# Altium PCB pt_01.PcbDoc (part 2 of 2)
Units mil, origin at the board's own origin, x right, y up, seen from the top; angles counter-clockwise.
Board outline 1456.69 x 1118.11 mil, 4 copper layers (Top Layer, med1, med2, Bottom Layer), stack 40.249 mil thick; 153 components, 173 nets, 567 pads, 147 vias.
Unrouted connection lines stored in the file: 22.
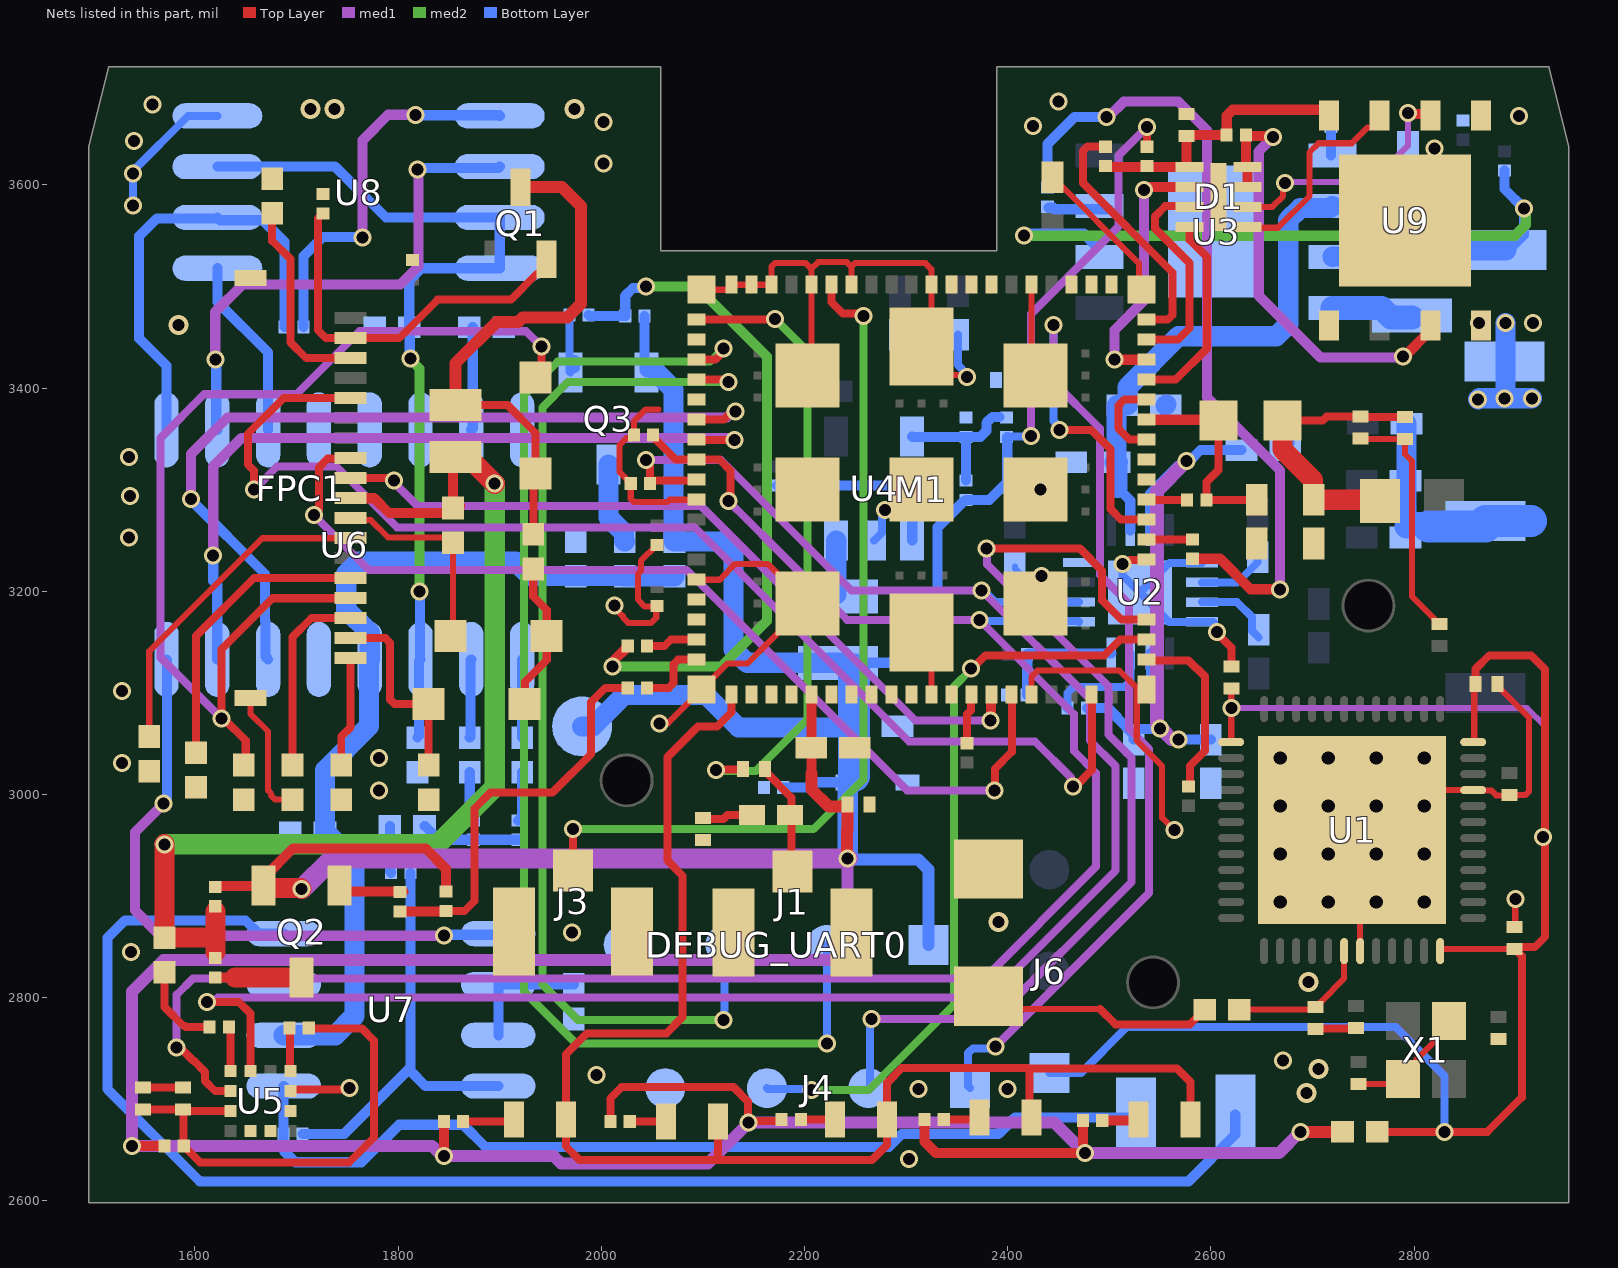
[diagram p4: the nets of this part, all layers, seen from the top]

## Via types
v1: diameter 17.72, hole 11.81, Top Layer to Bottom Layer, 121 vias
v2: diameter 25.98, hole 12.99, Top Layer to Bottom Layer, 16 vias
v3: diameter 19.68, hole 11.81, Top Layer to Bottom Layer, 8 vias
v4: diameter 25.59, hole 19.68, Top Layer to Bottom Layer, 1 vias
v5: diameter 27.56, hole 19.68, Top Layer to Bottom Layer, 1 vias

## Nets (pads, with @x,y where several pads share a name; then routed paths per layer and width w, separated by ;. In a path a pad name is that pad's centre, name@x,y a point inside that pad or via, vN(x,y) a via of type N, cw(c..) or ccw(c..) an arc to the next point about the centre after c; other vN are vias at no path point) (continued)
GND: C2.2 C3.2 C4.2 C5.2 C6.1 C7.2 C8.2 C9.2 C10.2 C11.2 C12.1 C13.2 C15.2 C16.2 C17.2 C19.2 C20.2 C21.1 C22.2 C23.2 C24.2 C26.2 C27.2 C28.2 C29.2 C30.2 C31.2 C32.2 C33.2 C34.2 C35.2 C43.2 C44.2 C45.1 C46.1 C48.1 C49.1 C50.1 C51.1 C52.1 C53.2 C54.2 C55.2 C56.1 C57.2 C58.2 C59.2 C63.1 D1.9 D3.1 D5.1 DEBUG_UART0.4 FPC1.8 FPC1.19 FPC1.20 GND.1 J1.2 J2.2 J3.2 J4.4 M1.1 M1.7 M1.13 M1.15 M1.20 M1.25 M1.30 M1.34 M1.36 M1.38 M1.39 M1.40 M1.41 M1.43 M1.46 M1.51 M1.55 M1.60 M1.66 M1.71 M1.76 M1.105 M1.106 M1.107 M1.108 M1.109 M1.110 M1.111 M1.112 M1.113 R9.1 R10.1 R14.1 R15.1 R17.2 R18.2 R19.2 R26.1 R28.2 R29.1 R30.2 U1.31 U1.45 U1.49 U2.1 U2.4 U2.17 U3.9 U4.2 U5.8 U5.9 U6.8 U6.13 U7.7 U8.4 U9.C4 U9.C5 U9.C8 U9.C9 X1.2 X1.4 | length 4047.3
  Top Layer w6: v1(1528,3102) v1@1530.24,3099.76 ; FPC1.20@1654.57,3094.78 1654.57,3079.43 1672,3062 1672,3004 1675,3001 1675,2999 1679,2995 1695.92,2995 C31.2@1696,2994.92 ; FPC1.8@1753,3271.94 1754.94,3270 1773,3270 1790,3253 1848.96,3253 C26.2@1854,3247.96 1854,3158.24 D3.1@1851.76,3156 ; v1(2013,3186) 2013,3183.83 2021.26,3175.57 2021.26,3174.24 2026.5,3169 2049,3169 2054,3174 2054,3184.49 R10.1@2054.51,3185 ; R17.2@2028.98,3304 2028.98,3291.02 2032,3288 2065,3288 2067.16,3290.16 M1.51@2093.54,3290.16 ; R17.2@2028.98,3306 2028.98,3306.41 2018,3317.39 2018,3344 2024.62,3350.62 2029.03,3350.62 2032,3353.59 R18.2@2032,3354 2032,3367.16 2043.84,3379 2056,3379 ; R10.1@2055,3185.49 R10.1@2054.51,3185 ; R9.1@2055,3245.49 2054.59,3245.49 2038.98,3229.88 2038.98,3219.98 2036,3217 2036,3192 2039,3189 2039,3188.51 2042.51,3185 R10.1@2054.51,3185 ; v1(2057,3070) 2065.31,3070 M1.60@2098.46,3103.15 2124.31,3129 2144,3129 M1.111@2202.8,3187.8 2163.59,3227 2132,3227 2116.42,3211.42 M1.55@2093.54,3211.42 ; M1.41@2098.46,3496.85 2125.09,3496.85 2127.99,3499.76 M1.40@2127.99,3501.77 M1.39@2147.68,3501.77 M1.38@2167.36,3501.77 2167.36,3519.49 2170.88,3523 2201,3523 2202.98,3521.02 2206.73,3517.27 ; M1.109@2202.8,3412.2 2206.73,3416.14 M1.36@2206.73,3501.77 2206.73,3517.27 ; M1.34@2246.1,3501.77 2246.1,3519.49 ; M1.112@2315,3159.25 2324.84,3149.41 M1.71@2324.84,3098.23 ; M1.108@2315,3440.75 M1.108@2324.84,3450.59 ; v1@2359.75,3413 2359.75,3415.68 2359.5,3415.93 2356.57,3413 2343.5,3413 2324.84,3431.65 M1.108@2324.84,3450.59 ; M1.76@2423.27,3098.23 2423.27,3115.73 2429.54,3122 2510,3122 2527,3105 2527,3053 2552,3028 2552,2977 v1(2564,2965) ; M1.25@2423.27,3501.77 2423.27,3416.14 M1.107@2427.2,3412.2 ; M1.105@2427.2,3187.8 2433,3193.59 v1(2433,3215) ; C10.2@2444,3607.46 2444.54,3607.46 2529,3523 2529,3499.39 M1.20@2531.54,3496.85 ; C17.2@2745,2715.18 2784.18,2715.18 X1.2@2788.82,2719.82 2802.55,2733.55 2802.55,2739.55 2820.36,2757.36 2820.36,2763.17 X1.4@2834.09,2776.91 ; U1.31@2746.87,2845.91 2746.87,2878.39 v2(2762.62,2894.13) ; C2.2@2747,3350.18 2747.09,3350.09 2790.91,3350.09 C3.2@2791,3350 2791,3335 2798,3328 2798,3194.82 2820.13,3172.7 2820.13,3170.73 2823.03,3167.82 C15.2@2825,3167.82 ; v2(2809.87,2988.62) 2825.61,3004.37 U1.45@2858.09,3004.37 2858.45,3004.01 2875.99,3004.01 2878.98,3001.02 2880.82,2999.18 C12.1@2898,2999.18 ; C16.2@2881.82,3109 2881.82,3107.03 2913,3075.86 2913,3002.87 2909.49,2999.35 C12.1@2894,2999.35 ; C22.2@2899,2869.65 2899.5,2870.15 2899.5,2896.5 v1(2900,2897) ; 2206.73,3517.27 2213.46,3524 2241.59,3524 2246.1,3519.49 ; 2246.1,3519.49 2249.62,3523 2319,3523 2320.98,3521.02 2324.84,3517.16 M1.30@2324.84,3501.77 M1.108@2324.84,3450.59
  Top Layer w7.87: C53.2@1549,2711.65 1549.09,2711.74 1587.91,2711.74 C54.2@1588,2711.82 ; C27.2@1570,2825 1570,2791 1589,2772 1590,2772 1591,2771 R30.2@1614.49,2771 ; U5.9@1694.06,2708 1695.56,2709.5 1750.5,2709.5 v1(1752,2711) ; v1(2279,3280) 2295,3280 M1.113@2315,3300 ; M1.108@2315,3440.75 2315,3440.56 2342.56,3413 M1.108@2343.5,3413 ; v1@2356.57,3413 2359.75,3413 v1@2360,3413 ; v1(2513,3227) 2515.66,3227 2519.66,3231 2536.37,3231 M1.7@2536.46,3231.09 ; M1.13@2536.46,3349.2 2519.8,3349.2 2509,3360 2509,3383 2515,3389 2536.02,3389 M1.15@2536.46,3388.57 ; v1(2606,3160) 2606,3158.77 2620,3144.77 C19.2@2620,3125.82 ; C21.1@2703,2769.18 2703.59,2769.77 2742.41,2769.77 C20.2@2743,2770.35 ; U9.C9@2751,3619 2751,3605 U9.C9@2791,3565 2820,3594 v1(2820,3636)
  Bottom Layer w6: C35.2@2407,3224.54 2407,3222.63 2414.63,3215 v1(2433,3215) ; C34.2@2673,3339 2679.12,3345.12 2679.12,3362.12
  Bottom Layer w7.87: v1(1538.96,3579.96) v1(1539,3611) 1539,3613.66 1593.34,3668 U8.4@1622.04,3668 ; U4.2@2268.6,3250 2276.47,3257.87 2276.47,3274.81 2279,3277.34 v1(2279,3280) ; C46.1@2351,3452.54 2351,3422.66 2359.5,3414.16 v1@2359.5,3411 ; v1(2513,3227) 2513,3215.8 U2.17@2530.03,3198.77 ; U2.1@2591,3228.09 2559.35,3228.09 U2.17@2530.03,3198.77 ; v1(2606,3160) 2606,3162.66 2602.81,3165.85 2602.81,3169.41 2602.22,3170 U2.4@2591,3170 2558.8,3170 U2.17@2530.03,3198.77
  Bottom Layer w19.68: C50.1@2555.46,3383 C50.1@2556.25,3383.79
  Bottom Layer w20: v1(2863,3389) 2864,3390 v1(2889,3390) ; v1(2890,3464) 2890,3391 v1(2889,3390) ; v1(2916,3390) v1(2889,3390)
  other v1: 2303,2641 2312,2710 2400,2710 1995,2724 2671,2738 1537,2845 1971,2864 1781,3004 1528,3031 1781,3036 1535,3253 1536,3294 2432.2,3300 1535,3332 2360,3411 2864,3464 2917,3464 2002,3621 1540,3643 2425,3658 2002,3662 2903,3668 1558,3679 2450,3682
  other v2: 2668.13,2894.13 2715.38,2894.13 2809.87,2894.13 2668.13,2941.38 2715.38,2941.38 2762.62,2941.38 2809.87,2941.38 2668.13,2988.62 2715.38,2988.62 2762.62,2988.62 2668.13,3035.87 2715.38,3035.87 2762.62,3035.87 2809.87,3035.87
  other v3: 2694.04,2706 2705.85,2729.62 2696.09,2815.55 2390.97,2874.6 1583.8,3461.9 1713.72,3674.5 1737.35,3674.5 1973.57,3674.5
GPS_RF1: C1.2 M1.42 | length 626.3
  Top Layer w7.87: M1.42@2093.54,3467.32 2093.88,3467.66 2170.66,3467.66 v1(2171,3468) ; v1(2113,3024) 2113.5,3024.5 2138.68,3024.5 C1.2@2139.18,3024 ; C1.2@2139.35,3028 2140.28,3028 2139.35,3028.92 C1.2@2139.35,3028
  med2 w7.87: v1(2113,3024) 2114,3023 2152,3023 2203,3074 2203,3436 v1(2171,3468)
INT_B: R19.1 R20.1 U2.8 | length 123.6
  Bottom Layer w10: R20.1@2419,3138 2419.26,3137.74 2419.26,3098.26 R19.1@2419.51,3098 ; R20.1@2419.49,3136 R20.1@2419.49,3136.41 ; R20.1@2419.51,3137.41 2420.48,3138.38 2420.89,3138.38 2421.18,3138.67 U2.8@2501.95,3138.67
KT_BUSY: U6.16 U7.1 | length 629
  med1 w10: v1(1569,2991) 1541,2963 1541,2886 1566,2861 v1(1845,2861)
  Bottom Layer w10: v1(1569,2991) 1569,2993.09 1572.5,2996.59 1572.5,3132.5 U6.16@1572,3133 ; v1(1845,2861) 1846,2862 1897.61,2862 U7.1@1898.61,2863
KT_DACL: C61.1 U6.10 | length 77.6
  Bottom Layer w10: C61.1@1870.5,3056.04 1871.25,3056.79 1871.25,3132.25 U6.10@1872,3133
KT_DACLout: C60.2 R37.2 R38.2 | length 97.6
  Bottom Layer w10: C60.2@1826,2969 1826.51,2969 1840.02,2955.49 R37.2@1874,2955.49 R38.2@1918,2955.49
KT_DACR: C62.1 U6.9 | length 77
  Bottom Layer w10: C62.1@1922,3056.04 U6.9@1922,3133
KT_KEY: U6.4
KT_POWER_Control: R5.2 SR5.1 SR6.1 | length 685
  Top Layer w10: v1(2011,3126) 2012.48,3127.48 2012.48,3132.09 2025.98,3145.59 R5.2@2025.98,3146
  med2 w10: v1(2011,3126) 2118,3126 2163,3171 2163,3431 2094,3500 v1(2044,3500)
  Bottom Layer w10: SR6.1@1987.51,3472 1988.48,3471 SR5.1@2023.49,3471 2023.49,3490.79 2031.22,3498.52 2042.52,3498.52 v1(2044,3500)
KT_RX: M1.48 U6.15 | length 754.6
  Top Layer w7.87: M1.48@2093.65,3349.11 2130.89,3349.11 v1(2131,3349)
  Top Layer w10: M1.48@2093.54,3349.21 M1.48@2093.65,3349.11
  med1 w10: v1(1618,3235) 1618,3323 1646,3351 2122.15,3351 2122.3,3350.85 2129.15,3350.85 v1(2131,3349)
  Bottom Layer w10: v1(1618,3235) 1618,3210.14 1622,3206.14 U6.15@1622,3133
KT_SPICS: U6.3 U8.1 | length 179.7
  Bottom Layer w10: U8.1@1622.04,3518 1622.04,3484.96 1672,3435 U6.3@1672,3359
KT_SPIDO: R40.1 U6.1 U8.2 | length 446.3
  Bottom Layer w10: U6.1@1572,3359 1572,3422 1545,3449 1545,3549.46 1562.54,3567 1621.04,3567 U8.2@1622.04,3568 1624.87,3565.17 1666.83,3565.17 1687.98,3544.02 R40.1@1687.98,3460
KT_SPISCK: U6.2 U8.6 | length 513.1
  med1 w10: v1(1620,3428) 1620,3475 1647,3502 1802,3502 1820,3520 1820,3614 v1(1819,3615)
  Bottom Layer w10: v1(1620,3428) 1621,3427 1621,3360 U6.2@1622,3359 ; v1(1819,3615) 1820.5,3616.5 1898.5,3616.5 U8.6@1900,3618
KT_TX: M1.47 U6.14 | length 828.7
  Top Layer w7.87: M1.47@2093.54,3368.9 2093.65,3369 2120.8,3369 2128.8,3377 v1(2132,3377)
  med1 w10: v1(1596,3291) 1596,3335 1632,3371 2123.38,3371 2129.38,3377 v1(2132,3377)
  Bottom Layer w10: v1(1596,3291) 1596,3290 1669,3217 1669,3170.86 1669.32,3170.54 1669.32,3135.68 U6.14@1672,3133
KT_USB+: U6.6
KT_USB-: U6.5
KT_V3V3: C58.1 C63.2 U6.11 U8.3 U8.7 U8.8 | length 898.4
  med2 w10: v1(1812,3429) 1812,3428.28 1821,3419.28 v1(1821,3199.96)
  Bottom Layer w10: U8.3@1622.04,3618 1738,3618 1788,3568 U8.7@1900,3568 U8.8@1900,3518 1823,3518 1811,3506 C63.2@1811,3460 1811.5,3459.5 1811.5,3429.5 v1(1812,3429) ; C58.1@1819,3056.04 1820.5,3057.54 1820.5,3131.5 U6.11@1822,3133 1821.5,3133.5 1821.5,3199.46 v1(1821,3199.96)
KT_VMCU: C57.1 C59.1 R39.1 SR4.2 U6.12 U7.6 | length 886.4
  Bottom Layer w20: U7.6@1687.39,2763 1738,2763 1757,2782 1757,2934.55 1728.55,2963 C57.1@1728.04,2963 1728.04,3024.04 1771.23,3067.23 1771.23,3132.23 U6.12@1772,3133 1772,3159.08 1749,3182.08 1749,3217.28 1760.72,3229 1916,3229 1930,3215 C59.1@1975,3214.96 SR4.2@2023,3214.96 ; SR4.2@2023,3214.96 R39.1@2072,3214.96
LED: LED1.K LED2.K LED3.K LED4.K LED5.K M1.61 | length 1406
  Top Layer w7.87: LED5.K@2114.59,2678 2114.59,2641.85 2113,2640.26 ; M1.61@2127.99,3098.23 2127.99,3080.99 2114,3067 2095,3067 2065,3037 2065,2935 2080,2920 2080,2781 2064,2765 1986,2765 1965,2744 LED2.K@1965,2680 1965,2653.87 1978.61,2640.26 2113,2640.26 ; 2420.59,2730.41 2566.59,2730.41 2580,2717 LED3.K@2580,2680 ; LED4.K@2423.59,2682 2421.59,2684 2421.59,2729.41 2420,2731 2296,2731 2281.18,2716.18 LED1.K@2281.18,2680 2281.18,2655.02 2266.42,2640.26 2113,2640.26
MAGPIO0: M1.21
MAGPIO1: M1.22
MAGPIO2: M1.23
MIPI_SCLK: M1.28
MIPI_SDATA: M1.27
MIPI_VIO: M1.29
NetC1_1: C1.1 J1.1 L1.1 | length 112.4
  Top Layer w7.87: C1.1@2161,3025 2161,3023.03 2186.99,2997.04 2186.99,2981.21 L1.1@2188.7,2979.5 ; L1.1@2185.7,2980 2186.93,2978.77 J1.1@2186.93,2925.04
NetC5_1: C5.1 FB1.2 M1.14 R1.1 | length 203.9
  Top Layer w7.87: FB1.2@2606.62,3368.88 FB1.2@2607.5,3368 2607.5,3319.5 2595.51,3307.51 R1.1@2595.51,3290 C5.1@2645,3290
  Top Layer w10: M1.14@2536.46,3368.88 FB1.2@2606.62,3368.88
NetC6_2: C6.2 L1.2 | length 55.9
  Top Layer w7.87: C6.2@2099,2977.65 C6.2@2100,2976.65 ; C6.2@2100,2975.82 2120.12,2975.82 2124.29,2980 2147.3,2980 L1.2@2151.3,2980 ; L1.2@2147.3,2979 L1.2@2148.3,2980
NetC7_1: C7.1 D1.5 R2.1 R32.2 R33.2 U9.C1 | length 279.6
  Top Layer w10: R32.2@2496,3618.49 2496.73,3617.76 D1.5@2578.92,3617.76 ; D1.5@2579,3617.68 D1.5@2578.92,3617.76 ; U9.C1@2716,3668.35 2716,3669.16 2711.16,3674 2621.35,3674 2615.49,3668.14 R2.1@2615.49,3649 2583.71,3649 2583.61,3648.91 2576.91,3648.91 C7.1@2576,3648 2576,3620.68 D1.5@2578.92,3617.76
NetC11_1: C11.1 M1.9 R3.2 | length 244.6
  Top Layer w7.87: v1(2451,3359) 2482,3359 2501,3340 2501,3281 2511.54,3270.46 M1.9@2536.46,3270.46
  Bottom Layer w7.87: C11.1@2410,3408 2410.5,3408.5 2444.5,3408.5 R3.2@2445,3409 2445,3367.66 2451,3361.66 v1(2451,3359)
NetC21_2: C21.2 L4.1 U1.30 | length 152.1
  Top Layer w6: L4.1@2619.73,2788.56 2700.73,2788.56 C21.2@2703,2790.82 2704.97,2790.82 2707.87,2793.73 2707.87,2795.7 2731.13,2818.95 U1.30@2731.13,2845.91
NetC25_1: C25.1 D2.1 D3.2 | length 147.6
  Top Layer w8: D2.1@1924.24,3089 1925,3089.76 1925,3111 1946.24,3132.24 1946.24,3181.76 1933,3195 C25.1@1933,3222
NetC25_2: C25.2 D4.2 L5.2 Q1.3 | length 543
  Top Layer w7.87: L5.2@1856.31,3383.49 1907.51,3383.49 1935,3356 D4.2@1935,3315.76 1933,3313.76 C25.2@1933,3256.08
  Top Layer w11.81: L5.2@1856.31,3383.49 1856.31,3424.31 1897,3465 1918,3465 1922.5,3469.5 1966.5,3469.5 1980,3483 1980,3579 1961.3,3597.7 Q1.3@1920.41,3597.7
NetC29_1: C29.1 FPC1.7 | length 319.1
  Top Layer w6: C29.1@1555,3066 1555,3141 1666.26,3252.26 FPC1.7@1753,3252.26
NetC36_1: C36.1 C37.1 C40.1 TP2.1 | length 225.1
  Bottom Layer w19.68: 2792.46,3264 C40.1@2792.46,3365
  Bottom Layer w23.62: 2792.46,3264 2794.46,3266 2812,3266 2814,3264
  Bottom Layer w31.5: 2814,3264 TP2.1@2870,3264 ; TP2.1@2870,3269 2914.95,3269
NetC39_2: C39.2 U2.2 | length 68.2
  Bottom Layer w7.87: U2.2@2591.2,3208.86 2591.56,3208.5 2625.88,3208.5 2646,3228.62 C39.2@2646,3233.54
NetC42_2: C42.2 U2.3 | length 78.2
  Bottom Layer w7.87: U2.3@2591.1,3189.23 2625.77,3189.23 2640.31,3174.69 2640.31,3161.15 C42.2@2647,3154.46
NetC47_1: C47.1 R25.1 R29.2 U4.5 | length 141.5
  Bottom Layer w10: U4.5@2306,3352.37 2306.37,3352 R29.2@2359,3352 ; C47.1@2359,3309.02 R29.2@2359,3352 ; 2391.64,3371.6 2384.86,3371.6 2379,3365.75 2379,3357.86 2373.14,3352 R29.2@2359,3352
NetC55_1: C55.1 U7.2 U7.3 | length 124.4
  Bottom Layer w10: U7.3@1898.61,2763 U7.2@1898.61,2813 U7.2@1898.61,2813 1972.96,2813.04 C55.1@1973,2813.08
NetC56_2: C56.2 U6.7 | length 101.6
  Bottom Layer w10: U6.7@1872,3359 1873.48,3360.48 C56.2@1873.48,3460
NetC60_1: C60.1 R36.2 | length 46.4
  Bottom Layer w10: C60.1@1791.92,2969 1791.92,2924.47 1792.98,2923.41 R36.2@1792.98,2923
NetC61_2: C61.2 R37.1 | length 49.1
  Bottom Layer w10: C61.2@1870.5,3021.96 1870.5,2977.6 1873.59,2974.51 R37.1@1874,2974.51
NetC62_2: C62.2 R38.1 | length 49.3
  Bottom Layer w10: R38.1@1918,2974.51 1918.41,2974.51 1922,2978.1 C62.2@1922,3021.96
NetD1_1: D1.1 U9.C2 | length 204.1
  Top Layer w6: D1.1@2636.09,3558.63 2636.9,3557.81 2665.81,3557.81 2697,3589 2697,3632 2706,3641 2738.65,3641 2754.24,3656.58 2759.16,3656.58 2766,3663.43 U9.C2@2766,3668.35
NetD1_2: D1.2 U9.C3 | length 250.9
  Top Layer w6: D1.2@2636.09,3578.31 2660.31,3578.31 2671,3589 2671,3600 v1(2673,3602)
  Top Layer w10: v1(2794,3671) 2795.33,3669.67 2814.67,3669.67 U9.C3@2816,3668.35 U9.C3@2816,3663.43
  med1 w6: v1(2673,3602) 2674,3603 2758,3603 2794,3639 v1(2794,3671)
  med2 w6: v1(2794,3671) v1@2795,3672
NetD1_3: D1.3 D1.4 R2.2 U9.C7 | length 450.4
  Top Layer w10: D1.4@2634.59,3617.68 2634.51,3617.76 R2.2@2634.51,3649 2635.48,3648 2660,3648 v1(2661,3647) ; D1.3@2636.09,3598 D1.4@2636.09,3617.68 ; v1(2789,3431) 2790.27,3431 2816,3456.73 U9.C7@2816,3461.65
  med1 w10: v1(2661,3647) 2647,3633 2647,3491 2708,3430 2788,3430 v1(2789,3431)
NetJ3_1: J3.1 M1.35 | length 859.1
  Top Layer w7.87: J3.1@1971.93,2925.04 1972,2925.11 v1(1972,2966) ; M1.35@2226.42,3501.77 2226.42,3484.58 2237.74,3473.26 2255.74,3473.26 v1(2258,3471)
  med1 w7.87: v1(1972,2966) v1@1973,2967
  med2 w7.87: v1(1972,2966) 2209,2966 2258,3015 v1(2258,3471)
NetL7_1: L7.1 U4.3 | length 55.7
  Bottom Layer w10: L7.1@2231.2,3196.8 L7.1@2233,3195
  Bottom Layer w20: L7.1@2231.2,3196.8 U4.3@2231.2,3250
NetL8_2: L8.2 U3.4 | length 82.5
  Bottom Layer w23.62: U3.4@2719.5,3479 2767.69,3479 2777.36,3469.32 L8.2@2798,3469.32
NetLED1_A: LED1.A LR1.1 | length 33.5
  Top Layer w7.87: LR1.1@2196.51,2680 LED1.A@2230,2680
NetLED2_A: LED2.A LR2.1 | length 50.6
  Top Layer w7.87: LR2.1@1864,2678 1911.82,2678 LED2.A@1913.82,2680
NetLED3_A: LED3.A LR3.1 | length 36.2
  Top Layer w10: LR3.1@2493,2679 2527.82,2679 LED3.A@2528.82,2680
NetLED4_A: LED4.A LR4.1 | length 36.2
  Top Layer w7.87: LR4.1@2337,2680 2370.41,2680 LED4.A@2372.41,2682
NetLED5_A: LED5.A LR5.1 | length 35.4
  Top Layer w8: LR5.1@2028,2678 LED5.A@2063.41,2678
NetM1_10: M1.10 R1.2 | length 40.1
  Top Layer w7.87: M1.10@2536.46,3290.14 M1.10@2536.46,3290.14 2576.42,3290.07 R1.2@2576.49,3290
NetQ2_1: Q2.1 SR3.2 | length 65
  Top Layer w7.87: Q2.1@1742.4,2910.28 Q2.1@1748.17,2904.51
  Top Layer w10: Q2.1@1748.17,2904.51 SR3.2@1805,2904.51
NetQ2_3: Q2.3 SR1.1 | length 85.1
  Top Layer w10: SR1.1@1620,2820 1639,2820 1639.28,2819.72
  Top Layer w19.68: 1639.28,2819.72 Q2.3@1705,2819.72
NetQ3_1: Q3.1 SR6.2 | length 64.5
  Bottom Layer w7.87: SR6.2@1968.49,3472 1968.49,3416.38 Q3.1@1969.6,3415.28
  Bottom Layer w10: Q3.1@1973.81,3420.07 Q3.1@1973.81,3427.36
NetQ3_3: Q3.3 SR4.1 | length 82.3
  Bottom Layer w20: Q3.3@2007,3324.72 2007,3272.66 2022.37,3257.29 2022.37,3249.67 SR4.1@2023,3249.04
NetR21_2: R21.2 U2.7 | length 108.6
  Bottom Layer w7.87: R21.2@2458.98,3085 2459,3100.14 2464.86,3106 2514.75,3106 2520.61,3111.86 U2.7@2520.61,3138.82
NetR24_2: R24.2 U4.1 | length 180
  Bottom Layer w10: R24.2@2173,3304 2294,3304 2306,3292 U4.1@2306,3250
NetR26_2: R26.2 U3.1 | length 28
  Bottom Layer w10: U3.1@2718,3629 R26.2@2718,3657
NetR27_2: R27.2 U3.7 | length 59.5
  Bottom Layer w10: R27.2@2440.38,3577.52 2444.71,3577.52 2446.24,3576 U3.7@2499.26,3576
NetR30_1: R30.1 U5.1 | length 41.3
  Top Layer w7.87: U5.1@1635,2727.69 R30.1@1634.99,2768.99
NetR31_1: R31.1 U5.10 | length 42.8
  Top Layer w7.87: R31.1@1692.98,2770 1693.52,2769.46 1693.52,2728.23 U5.10@1694.06,2727.69
NetR35_1: R35.1 R36.1 U7.4 | length 420.7
  Bottom Layer w10: R35.1@1706.02,2666 1747,2666 1812,2731 ; R36.1@1812,2923 1812,2728 1827,2713 U7.4@1898.61,2713
NetR40_2: R40.2 U8.5 | length 377.9
  med1 w10: v1(1765,3548) 1765,3644 1790,3669 v1(1817,3669)
  Bottom Layer w10: R40.2@1707,3460 1707,3530 1725.81,3548.81 1764.19,3548.81 v1(1765,3548) ; v1(1817,3669) 1817.5,3668.5 1899.5,3668.5 U8.5@1900,3668
nRESET: J4.1 R3.1 | length 910.5
  med1 w7.87: v1(2388,2752) 2539,2903 2539,3045 2519.5,3064.5 2519.5,3187.5 2491,3216 2491,3360 2445,3406 v1(2445,3462)
  Bottom Layer w7.87: J4.1@2363,2711 2361,2713 2361,2745.5 2365.61,2750.12 2386.12,2750.12 v1(2388,2752) ; R3.1@2445,3428.02 v1(2445,3462)
P0.00: M1.56
P0.01: M1.57
P0.02: M1.58 R5.1 | length 51.2
  Top Layer w7.87: R5.1@2045,3146 2062,3146 2068.36,3152.36 M1.58@2093.54,3152.36
P0.03: M1.59 R6.1 | length 70.8
  Top Layer w7.87: R6.1@2045,3105 2066.39,3105 2071,3109.61 2071,3128.06 2075.61,3132.68 M1.59@2093.54,3132.68
P0.05: M1.62
P0.06: M1.63
P0.07: M1.64
P0.08: M1.67
P0.09: M1.68
P0.10: M1.69
P0.11: M1.70
P0.12: M1.72
P0.13/AIN0: M1.73 R8.1 | length 49.9
  Top Layer w7.87: R8.1@2359,3050.51 2360,3051.51 2360,3079 2363.86,3082.86 2363.86,3097.88 M1.73@2364,3098.02
  Top Layer w10: M1.73@2364,3098.02 M1.73@2364.21,3098.23
P0.14/AIN1: FPC1.10 M1.74 | length 755.5
  Top Layer w7.87: FPC1.10@1753,3311.31 1793.69,3311.31 v1(1796,3309)
  Top Layer w10: v1(2383,3073) 2383.45,3073.45 2383.45,3097.78 M1.74@2383.9,3098.23
  med1 w7.87: v1(1796,3309) 1796,3307 1819,3284 2098,3284 2309,3073 v1(2383,3073)
P0.15/AIN2: FPC1.11 M1.75 | length 967.5
  Top Layer w7.87: v1(1717,3275) 1717,3275.66 1722,3280.66 1722,3322 1730.7,3330.7 1752.7,3330.7 FPC1.11@1753,3331 ; v1(2387,3004) 2387.24,3004.24 2387.24,3025.24 2404,3042 2404,3097.81 M1.75@2403.58,3098.23
  med1 w7.87: v1(1717,3275) 1771,3221 2084,3221 2301,3004 v1(2387,3004)
P0.18/AIN5: FPC1.14 M1.79 | length 1223.1
  Top Layer w7.87: v1(1658,3300) 1657.88,3300.12 1657.88,3318.86 1652,3324.74 1652,3355 1687.06,3390.06 FPC1.14@1753,3390.06 ; v1(2464,3008) 2466.66,3008 2483,3024.34 2483,3097.55 M1.79@2482.32,3098.23
  med1 w7.87: v1(1658,3300) 1681,3323 1739,3323 1799,3263 2092,3263 2303,3052 2427,3052 2462.12,3016.88 2462.12,3009.88 v1(2464,3008)
P0.20/AIN7: M1.2 R4.1 | length 179.1
  Top Layer w7.87: M1.2@2536.46,3132.66 2537.12,3132 2578,3132 2594,3116 2594,3043 2579.15,3028.15 2579.15,3009.15 R4.1@2578,3008
P0.23: M1.8 R7.1 | length 45.6
  Top Layer w7.87: M1.8@2536.46,3250.77 2536.58,3250.9 2581.88,3250.9 R7.1@2582,3251.02
P0.24: M1.11
P0.25: M1.12
P0.26: DEBUG_UART0.2 M1.44 | length 1251.2
  Top Layer w7.87: M1.44@2093.54,3427.95 2112.39,3427.95 2117,3432.57 2117,3433 2120,3436 v1(2120,3439)
  med2 w7.87: v1(2120,3439) 2107,3426 1957,3426 1924,3393 1924,2806 1975,2755 v1(2222,2755)
  Bottom Layer w7.87: v1(2222,2755) DEBUG_UART0.2@2222,2852
P0.27: DEBUG_UART0.3 M1.45 | length 1061.1
  Top Layer w7.87: M1.45@2093.54,3408.27 2117.73,3408.27 2118.12,3407.88 2123.12,3407.88 v1(2125,3406)
  med2 w7.87: v1(2120,2778) 1977,2778 1942,2813 1942,3381 1967,3406 v1(2125,3406)
  Bottom Layer w7.87: v1(2120,2778) 2121,2779 2121,2851 DEBUG_UART0.3@2122,2852
P0.30/SDA: M1.49 R18.1 U2.9 U5.2 | length 1892.9
  Top Layer w7.87: v1(1582,2751) 1585.2,2751 1598.59,2737.6 1599.4,2737.6 1610,2727 1610,2718 1620,2708 U5.2@1635,2708 ; R18.1@2051.02,3354 2053.05,3351.97 2053.05,3349.95 2073.47,3329.53 M1.49@2093.54,3329.53 2116.47,3329.53 2127.26,3318.74 2127.26,3291.26 v1(2125,3289)
  med1 w7.87: v1(1582,2751) 1582,2803 1598,2819 2377,2819 2487,2929 2487,3021 2465,3043 2465,3079 v1(2372,3172) 2242,3172 2169.81,3244.19 2144.53,3269.46 v1(2125,3289)
  Bottom Layer w7.87: v1(2372,3172) 2373.46,3170.54 2469.41,3170.54 U2.9@2470,3169.95
P0.31/SCL: M1.50 R17.1 U2.10 U5.12 | length 1931.5
  Top Layer w7.87: v1(1612,2796) 1643,2796 1654.69,2784.31 U5.12@1654.69,2727.69 ; v1(2044,3329) 2044,3326.34 2048,3322.34 R17.1@2048,3306 ; R17.1@2053,3309 2092.7,3309 M1.50@2093.54,3309.84
  med1 w7.87: v1(1612,2796) 1614.26,2798.26 1620.78,2798.26 1622.52,2800 2381,2800 2506,2925 2506,3028 2481,3053 2481,3094 v1(2374,3201) 2246,3201 2118,3329 v1(2044,3329)
  Bottom Layer w7.87: v1(2374,3201) 2376.13,3201 2387.66,3189.48 U2.10@2469.95,3189.48
PIN_CHARGE: R7.2 R27.1 | length 807.8
  Top Layer w10: R7.2@2582,3232 2609,3232 2639,3202 v1(2668,3202)
  med1 w10: v1(2497,3667) 2499.09,3667 2514.09,3682 2568,3682 2596,3654 2596,3391 2668,3319 v1(2668,3202)
  Bottom Layer w10: R27.1@2439,3598.48 2439,3640 2466,3667 v1(2497,3667)
Q_INA1: U5.5
Q_INA2: U5.6
RESE: FPC1.17 Q1.2 R15.2 | length 382.9
  Top Layer w7.87: R15.2@1726,3572 1725.59,3572 1723.56,3569.97 1723.56,3569.56 1721,3567 1721,3457 1728.89,3449.11 FPC1.17@1753,3449.11 1801.08,3449.11 1838.97,3487.01 1911.01,3487.01 1936.51,3512.51 1940.09,3512.51 1946,3518.42 Q1.2@1946,3527
RF: J2.1 L4.2 | length 220.7
  Top Layer w6: J2.1@2390,2799.96 2400.96,2789 2490.94,2789
  Top Layer w7.87: 2490.94,2789 2506.16,2773.78 2579.24,2773.78 2593.45,2788 L4.2@2593.96,2788
S_VDD: C53.1 C54.1 R31.2 R34.1 U5.3 | length 493.5
  Top Layer w7.87: C53.1@1549,2690 1587.82,2690 C54.1@1588,2690.18 ; U5.3@1635,2688.32 1592.65,2688.32 1589.97,2691 1588,2691 1588.51,2690.49 1588.51,2654.51 R34.1@1589.02,2654 1589.02,2653.59 1591.05,2651.56 1591.46,2651.56 1605.02,2638 1751.79,2638 1776,2662.21 1776,2758 1764.41,2769.59 1712,2769.59 R31.2@1712,2770
SCRE_POWER_Control: R6.2 SR2.1 SR3.1 | length 398.3
  Top Layer w7.87: SR2.1@1847,2885.49 1865.49,2885.49 1875,2895 1875,2986 1891,3002 1952,3002 1990,3040 1990,3091 2004,3105 R6.2@2025.98,3105
  Top Layer w10: SR3.1@1802,2885 1846.51,2885 SR2.1@1847,2885.49
Screen_3V3: C26.1 C27.1 FPC1.9 L5.1 R16.1 SR1.2 | length 1034.8
  Top Layer w10: FPC1.9@1753,3291.63 1776.37,3291.63 1791,3277 1848.96,3277 C26.1@1854,3282.04 1854,3330 L5.1@1856.31,3332.31
  Top Layer w19.68: C27.1@1570,2859.08 1614.57,2859.08 ; 1620,2845 R16.1@1620,2885
  Top Layer w20: C27.1@1570,2859.08 v1(1570,2951) ; C26.1@1855.13,3283.18 C26.1@1855.96,3284 ; L5.1@1856.31,3332.31 1862.06,3326.56 1874.44,3326.56 v1(1895,3306)
  med2 w20: v1(1570,2951) 1839,2951 1895,3007 v1(1895,3306)
SIM_1V8: M1.19 R32.1 | length 249.5
  Top Layer w7.87: R32.1@2496,3637.51 2495.51,3638 2478.61,3638 2474,3633.39 2474,3602 2562,3514 2562,3471.94 2557.39,3467.32 M1.19@2536.46,3467.32
SIM_CLK: D1.7 M1.18 | length 209.8
  Top Layer w7.87: M1.18@2536.46,3447.62 2567.62,3447.62 2579,3459 2579,3523 2545,3557 2545,3569 2555,3579 2578.32,3579 D1.7@2579,3578.31
SIM_IO: D1.6 M1.17 | length 256.7
  Top Layer w10: v1(2505,3428) M1.17@2536.43,3427.97 ; v1(2534,3595) 2536.09,3595 2539.09,3598 D1.6@2579,3598
  med1 w10: v1(2505,3428) 2505,3457 2534,3486 v1(2534,3595)
SIM_RST: D1.8 M1.16 | length 199
  Top Layer w7.87: M1.16@2536.46,3408.25 2565.25,3408.25 2596,3439 2596,3529 2579,3546 D1.8@2579,3558.63
SPEAK_VO1: R35.2 S1.1 U7.5 | length 943.6
  Bottom Layer w10: U7.5@1687.39,2713 1687,2712.61 R35.2@1687,2666 1687,2650 1699,2638 1764,2638 1801,2675 1864,2675 1886,2653 2283,2653 2296,2666 2391,2666 2407,2682 S1.1@2526,2682
SPEAK_VO2: S2.1 U7.8 | length 1521.4
  Bottom Layer w10: U7.8@1687.39,2863 1662.82,2863 1649.82,2876 1531,2876 1514,2859 1514,2710 1603,2621 1603.14,2621 1605.14,2619 2577.68,2619 2624,2665.32 S2.1@2624,2685
SWDCLK: J4.3 M1.3 | length 741.9
  Top Layer w7.87: v1(2364,3124) 2365,3124 2378,3137 2495,3137 2510.35,3152.35 M1.3@2536.46,3152.35
  med2 w7.87: v1(2207,2709) 2263,2709 2347,2793 2347,3106.2 2364,3123.2 v1(2364,3124)
  Bottom Layer w7.87: J4.3@2163,2711 2164,2710 2206,2710 v1(2207,2709)
SWDIO: J4.2 M1.4 | length 971.8
  Top Layer w7.87: v1(2379,3242) 2471,3242 2493,3220 2493,3191 2511.97,3172.03 M1.4@2536.46,3172.03
  med1 w7.87: v1(2266,2779) 2387,2779 2522,2914 2522,3036 2499,3059 2499,3107 2379.74,3226.26 2379.74,3241.26 v1(2379,3242)
  Bottom Layer w7.87: J4.2@2263,2711 2264.5,2712.5 2264.5,2777.5 v1(2266,2779)
TEMP/VBAT: U2.12
V_OUT: C33.1 C50.2 U2.14 U3.2 | length 495.2
  Bottom Layer w10: 2508,3302 2520.61,3289.39 U2.14@2520.61,3260.17
  Bottom Layer w20: C33.1@2505.46,3327 C33.1@2508.37,3327 ; C33.1@2506.37,3327 2507,3327.63 2507,3382.37 2507.63,3383 2517.46,3383 2518.09,3383.63 2518.09,3401.09 2568,3451 2664.28,3451 2676,3462.72 2676,3565.47 2687.72,3577.19 2717.69,3577.19 U3.2@2719.5,3579 ; C33.1@2507.37,3327 2508,3326.37 2508,3302
VBAT: BAT.1 C51.2 L8.1 R23.1 U3.3 U3.6 | length 912.9
  med2 w10: v1(2416,3550) 2899,3550 2909.86,3560.86 2909.86,3569.14 2909.48,3569.52 2909.48,3575.52 v1(2908,3577)
  Bottom Layer w10: v1(2416,3550) 2420,3550 2422,3552 2474.75,3552 2485,3541.75 ; R23.1@2889,3614 2889,3596 v1(2908,3577) 2908,3550.69 2893.31,3536 BAT.1@2891,3536
  Bottom Layer w19.68: U3.3@2719.5,3529 2719.88,3529.38 2768.07,3529.38 2774.03,3535.34 2794.54,3535.34 2890.34,3535.34 BAT.1@2891,3536 ; L8.1@2794.54,3538.14 C51.2@2794.54,3593
VCOM: C32.1 FPC1.1 | length 110.3
  Top Layer w7.87: C32.1@1744,3029 1744,3057 1753,3066 FPC1.1@1753,3134.15 FPC1.1@1754,3133.15
VDD_3V3: 1.1 C8.1 C9.1 C47.2 C48.2 C49.2 D5.2 DEBUG_UART0.1 L7.2 LR1.2 LR2.2 LR3.2 LR4.2 LR5.2 M1.65 Q2.2 Q3.2 R12.2 R16.2 R25.2 R33.1 R34.2 R39.2 SR2.2 SR5.2 | length 5723.7
  Top Layer w7.87: Q2.2@1667.6,2910.28 Q2.2@1667.6,2918.15 ; LR5.2@2008.98,2678 2008.98,2700.98 2020,2712 2130,2712 2144.33,2697.67 2144.33,2677.67 v1(2145,2677) 2146.5,2678.5 2175.99,2678.5 LR1.2@2177.49,2680 ; R33.1@2537,3637.51 v1(2537,3657)
  Top Layer w10: v1(1538,2654) R34.2@1570,2654 ; R16.2@1620,2909.02 1620.97,2909.99 1626.24,2909.99 1667.32,2910 Q2.2@1667.6,2910.28 ; Q2.2@1667.6,2918.15 1696.45,2947 1827,2947 1847,2927 SR2.2@1847,2904.51 ; v1(1845,2644) LR2.2@1844.98,2678 ; 2206.73,3020.91 M1.65@2206.73,3098.23 ; LR4.2@2317.98,2680 2317.98,2658.62 2329.6,2647 v1(2476,2647) 2476,2649.09 2474,2651.09 LR3.2@2473.98,2679
  Top Layer w11.81: 2206.73,3020.91 2206.73,3005.33 2224.03,2988.03 C8.1@2242.18,2988.03 ; C8.1@2242.18,2990 C8.1@2242.18,2988.03 ; v1(2242.47,2937) 2242,2937.47 2242,2965 2242.18,2965.18 C8.1@2242.18,2988.03 ; v1(2688,2668) R12.2@2729.47,2668
  Top Layer w19.68: Q2.2@1667.6,2910.28 1667.6,2909.97 1669.57,2908 1704,2908 v1(1705,2907)
  med1 w7.87: v1(2423,3353) 2423,3473 2509,3559 2509,3629 v1(2537,3657)
  med1 w11.81: v1(2242.47,2937) 2242.47,2843.92 2235.56,2837 1569,2837 1538,2806 v1(1538,2654) 1833.4,2654 1843.4,2644 1953.3,2644 1960.3,2637 2105,2637 v1(2145,2677) 2446,2677 v1(2476,2647) 2667,2647 v1(2688,2668)
  med1 w20: v1(1705,2907) 1735,2937 v1(2242.47,2937)
  Bottom Layer w7.87: R25.2@2399,3352 2399.5,3352.5 2422.5,3352.5 v1(2423,3353)
  Bottom Layer w10: SR5.2@2042.51,3471 2042.51,3417.17 Q3.2@2044.4,3415.28 ; C48.2@2179.02,3007 2206.76,3007 2211.76,3012 D5.2@2242.47,3012 ; L7.2@2241.81,3129.65 2312.65,3129.65 2331,3148 2331,3263 2357.03,3289.03 2358.03,3289.03 C47.2@2359,3290 2382,3290 2399.5,3307.5 R25.2@2399.5,3352
  Bottom Layer w11.81: 1.1@1981,3067 1.1@1982,3068 ; v1(2242.47,2937) 2243.47,2936 2312,2936 2322,2926 DEBUG_UART0.1@2322,2852 ; C49.2@2247.54,3066 C49.2@2248.54,3067
  Bottom Layer w19.68: 1.1@1981,3067 1991.65,3067 2022.65,3098 2103,3098 2135,3066 C49.2@2247.54,3066
  Bottom Layer w20: Q3.2@2054.4,3415.28 2071,3398.68 2071,3257.66 2071.37,3257.29 2071.37,3249.67 R39.2@2072,3249.04 2118.28,3249.04 2130,3237.32 2130,3143 2143.35,3129.65 L7.2@2233,3129.65 2241.81,3129.65 L7.2@2248.54,3122.92 ; v1(2242.47,2937) D5.2@2242.47,3012 2242.47,3012.32 D5.2@2248.54,3018.38
  Bottom Layer w31.5: D5.2@2248.54,3018.38 C49.2@2248.54,3067 L7.2@2248.54,3122.92
VDD_nRF: C2.1 C3.1 C4.1 FB1.1 R11.1 | length 278.5
  Top Layer w7.87: FB1.1@2670.5,3368 2710,3368 2713.82,3371.82 C2.1@2747,3371.82 2747.09,3371.73 2790.91,3371.73 C3.1@2791,3371.64 C3.1@2791.18,3371.47 ; R11.1@2765,3290 R11.1@2766,3289
  Top Layer w20: FB1.1@2670.5,3368 2670.5,3339.5 2700.37,3309.63 2700.37,3290.63 C4.1@2701,3290 R11.1@2765,3290
VDD_nrf52832: C16.1 C19.1 C22.1 J6.1 R12.1 U1.13 U1.36 U1.48 | length 1786.3
  Top Layer w6: U1.13@2619.91,3051.61 2619.95,3051.66 v1(2620,3085) v1(2620,3085) C19.1@2620,3104.18 ; U1.36@2825.61,2845.91 2825.61,2847.13 2826.48,2848 C22.1@2899,2848 ; U1.48@2858.09,3051.61 2858.27,3051.61 2859.14,3052.48 C16.1@2859.14,3107.96
  Top Layer w7.87: R12.1@2763.55,2668 v1(2830,2668) 2872,2668 2906,2702 2906,2841 C22.1@2902.94,2844.06 ; C16.1@2859.14,3107.96 C16.1@2860.18,3109 2860.46,3109.28 2860.46,3123.46 2874,3137 2915,3137 2929,3123 2929,2860 2918.68,2849.68 2900.68,2849.68 C22.1@2899,2848
  med1 w6: v1(2620,3085) 2911,3085 2928,3068 2928,2960 2927,2959 v1(2927,2958)
  Bottom Layer w7.87: J6.1@2441,2726 2472,2726 2517,2771 2782,2771 2830,2723 v1(2830,2668)
VGH: C28.1 D4.1 FPC1.4 | length 1032.5
  Top Layer w8: C28.1@1648,3029.04 1650,3031.04 1650,3053 1628,3075 v1(1626,3075) 1626,3143 1676.2,3193.2 FPC1.4@1753,3193.2 ; D4.1@1935,3410.24 1941,3416.24 v1(1941,3441)
  med1 w8: v1(1626,3075) 1566,3135 1566,3351 1609,3394 1700,3394 1762,3456 1926,3456 v1(1941,3441)
VGL: C24.1 D2.2 FPC1.2 | length 196.3
  Top Layer w7.87: FPC1.2@1753,3153.83 1787.39,3153.83 1792,3149.22 1792,3093.61 1796.61,3089 D2.2@1829.76,3089 1830,3088.76 C24.1@1830,3029
VRECT_POWER: C34.1 C43.1 C44.1 R21.1 U2.6 U2.15 | length 643.3
  med1 w13.78: v1(2568,3054) 2567.25,3054.75 2561.31,3054.75 2551.07,3065 v1(2550,3065) 2550,3066.07 2547,3069.07 2547,3298.93 v1(2576.15,3328.08)
  Bottom Layer w10: R21.1@2478,3085 2498.97,3085 2507.48,3076.48 2507.48,3075.44 C43.1@2524,3058.92 ; C43.1@2524,3054 C43.1@2524,3058.92 ; U2.6@2540.29,3138.84 2540.76,3138.37 2540.76,3124.49 2540.99,3124.26 2540.99,3094.84 2548.52,3087.31 2548.52,3066.48 v1(2550,3065) 2549.55,3064.55 2529.63,3064.55 C43.1@2524,3058.92 ; U2.15@2540.34,3260.17 2540.34,3296.34 2567.24,3323.24 2568.69,3323.24 2573.53,3328.08 v1(2576.15,3328.08) 2578.77,3328.08 2589.69,3339 C34.1@2630.08,3339 ; v1(2568,3054) C44.1@2600,3054
VSH1: C30.1 FPC1.5 | length 291.3
  Top Layer w7.87: C30.1@1601,3041.04 1601,3156 1657.89,3212.89 1751.22,3212.89 1752.11,3212 FPC1.5@1753,3212.89
VSH2: C23.1 FPC1.16 | length 199.9
  Top Layer w7.87: C23.1@1676,3571.96 1676,3545 1694,3527 1694,3445 1709.57,3429.43 FPC1.16@1753,3429.43
VSL: C31.1 FPC1.3 | length 190.7
  Top Layer w7.87: C31.1@1696,3029 1696,3155 1714.52,3173.52 FPC1.3@1753,3173.52
pads on no net: D1. FPC1.6 M1.26 M1.31 M1.32 M1.33 M1.37 M1.81 M1.82 M1.83 M1.84 M1.85 M1.86 M1.87 M1.88 M1.89 M1.90 M1.91 M1.92 M1.93 M1.94 M1.95 M1.96 M1.97 M1.98 M1.99 M1.100 M1.101 M1.102 M1.103 M1.104 U1.2 U1.3 U1.44 U1.47 U3.8 U5.4 U5.7 U5.11 U9.C6

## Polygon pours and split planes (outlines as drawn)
GND on Bottom Layer "GND_L04_P017" (solid, remove dead copper, pour order 17): 1498,3636 1505.35,3663.16 1520,3717 2060,3717 2064,3713 2062,3711 2062,3530 2388,3530 2393,3535 2393,3715 2934,3715 2955,3634.84 2955,2596 2954,2595 1496,2595
VBAT on Bottom Layer "VBAT_L04_P018" (solid, remove dead copper, pour order 18): 2694.5,3507 2857.5,3507 2863.5,3501 2869.5,3507 2936.5,3507 2936.5,3583.9 2893.5,3631 2828.5,3631 2818.5,3621 2780.5,3621 2780.5,3576 2747.5,3543 2694.5,3543
AC1 on Bottom Layer "AC1_L04_P002" (solid, pour order 2): 2774,3226.48 2774,3398 2715,3398 2715,3333 2695,3313 2564.54,3313 2551,3299.46 2551,3225.48
NetC36_1 on Bottom Layer "NETC36_1_L04_P001" (solid, pour order 1): 2932.26,3199 2810,3199 2774,3235 2774,3398 2826,3398 2867,3357 2932.26,3357
AC2 on Bottom Layer "AC2_L04_P000" (solid, pour order 0): 2553,3154 2796,3154 2804.17,3176 2932.49,3176 2932.55,3036 2828,3036 2789,3075 2553,3075
+5V on Bottom Layer "+5V_L04_P005" (solid, pour order 5): 2513,3475.84 2513,3534 2428,3534 2412,3518 2247,3518 2215,3486 2215,3359 2199,3359 2199,3313 2264,3313 2264,3466 2273.84,3475.84
GND on med1 "GND_L02_P015" (solid, remove dead copper, pour order 15): 1493,3638 1500.35,3665.16 1515,3719 2055,3719 2059,3715 2057,3713 2057,3532 2383,3532 2388,3537 2388,3717 2929,3717 2950,3636.84 2950,2598 2949,2597 1491,2597
GND on med2 "GND_L03_P016" (solid, remove dead copper, pour order 16): 1495,3638 1502.35,3665.16 1517,3719 2057,3719 2061,3715 2059,3713 2059,3532 2385,3532 2390,3537 2390,3717 2931,3717 2952,3636.84 2952,2598 2951,2597 1493,2597
GND on Top Layer "GND_L01_P014" (solid, remove dead copper, pour order 14): 1496,3634 1503.35,3661.16 1518,3715 2058,3715 2062,3711 2060,3709 2060,3528 2386,3528 2391,3533 2391,3713 2932,3713 2953,3632.84 2953,2594 2952,2593 1494,2593

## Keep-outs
Keep-Out Layer:
  the board outline again, w0.5

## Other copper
Top Layer:
  pour cut-out: 2144,2896 2144,2831 2232,2831 2232,2896
Bottom Layer:
  pour cut-out: 2461,2905 2460,2904 2460,2846 2426,2846 2427,2847 2427,2909
  pour cut-out: 2774,3521 2774,3490 2840,3490 2840,3520

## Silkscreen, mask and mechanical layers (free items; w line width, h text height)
Bottom Overlay:
  text "B_CLK" at 2432,2912 h30
  text "TX" at 2150,2885 h30
  text "RX" at 2253,2885 h30
  text "GND" at 2060,2882 h30
  text "PT_01" at 2901,2824 h30
  text "3V3" at 2362,2789 h30
  text "05V20250422" at 2908,2776 h60
  text "B_DIO" at 2512,2771 h30
  text "CLK" at 2209,2646 h30
  text "RSET" at 2419,2646 h30
  text "DIO" at 2302,2645 h30
  text "GND" at 2091,2642 h30
Mechanical 13:
  the board outline again, w0.5
Mechanical 15:
  lines w0.5: 1657.05,3488.33 1657.05,3696.99 1865.71,3696.99 1865.71,3488.33 1657.05,3488.33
